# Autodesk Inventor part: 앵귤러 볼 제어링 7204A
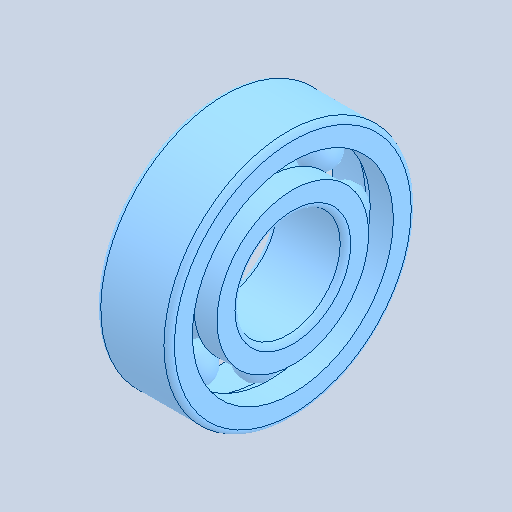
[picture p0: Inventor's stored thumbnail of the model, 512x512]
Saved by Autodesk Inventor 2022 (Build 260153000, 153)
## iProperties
Created: 2024-11
Part Number: 앵귤러 볼 제어링 7204A
Material: 강철, 연강
Description: 앵귤러 콘택트 볼 베어링
Document SubType Name: Modeling
Designer: PC-12
Density: 7.85 g/cm^3
Appearance: 기본값
Author: jhkim
Sending System: Autodesk Inventor 2025
Preprocessor: ST-DEVELOPER v20
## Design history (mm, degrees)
node "앵귤러 볼 제어링 7204A1"
node "솔리드1"
node "솔리드2"
node "솔리드3"
node "솔리드4"
node "솔리드5"
node "솔리드6"
node "솔리드7"
node "솔리드8"
node "솔리드9"
node "솔리드10"
body "Solid1"
node "Solid1:1"
node "Solid1:2"
node "Solid1:3"
node "Solid1:4"
node "Solid1:5"
node "Solid1:6"
node "Solid1:7"
node "Solid1:8"
node "Solid1:9"
